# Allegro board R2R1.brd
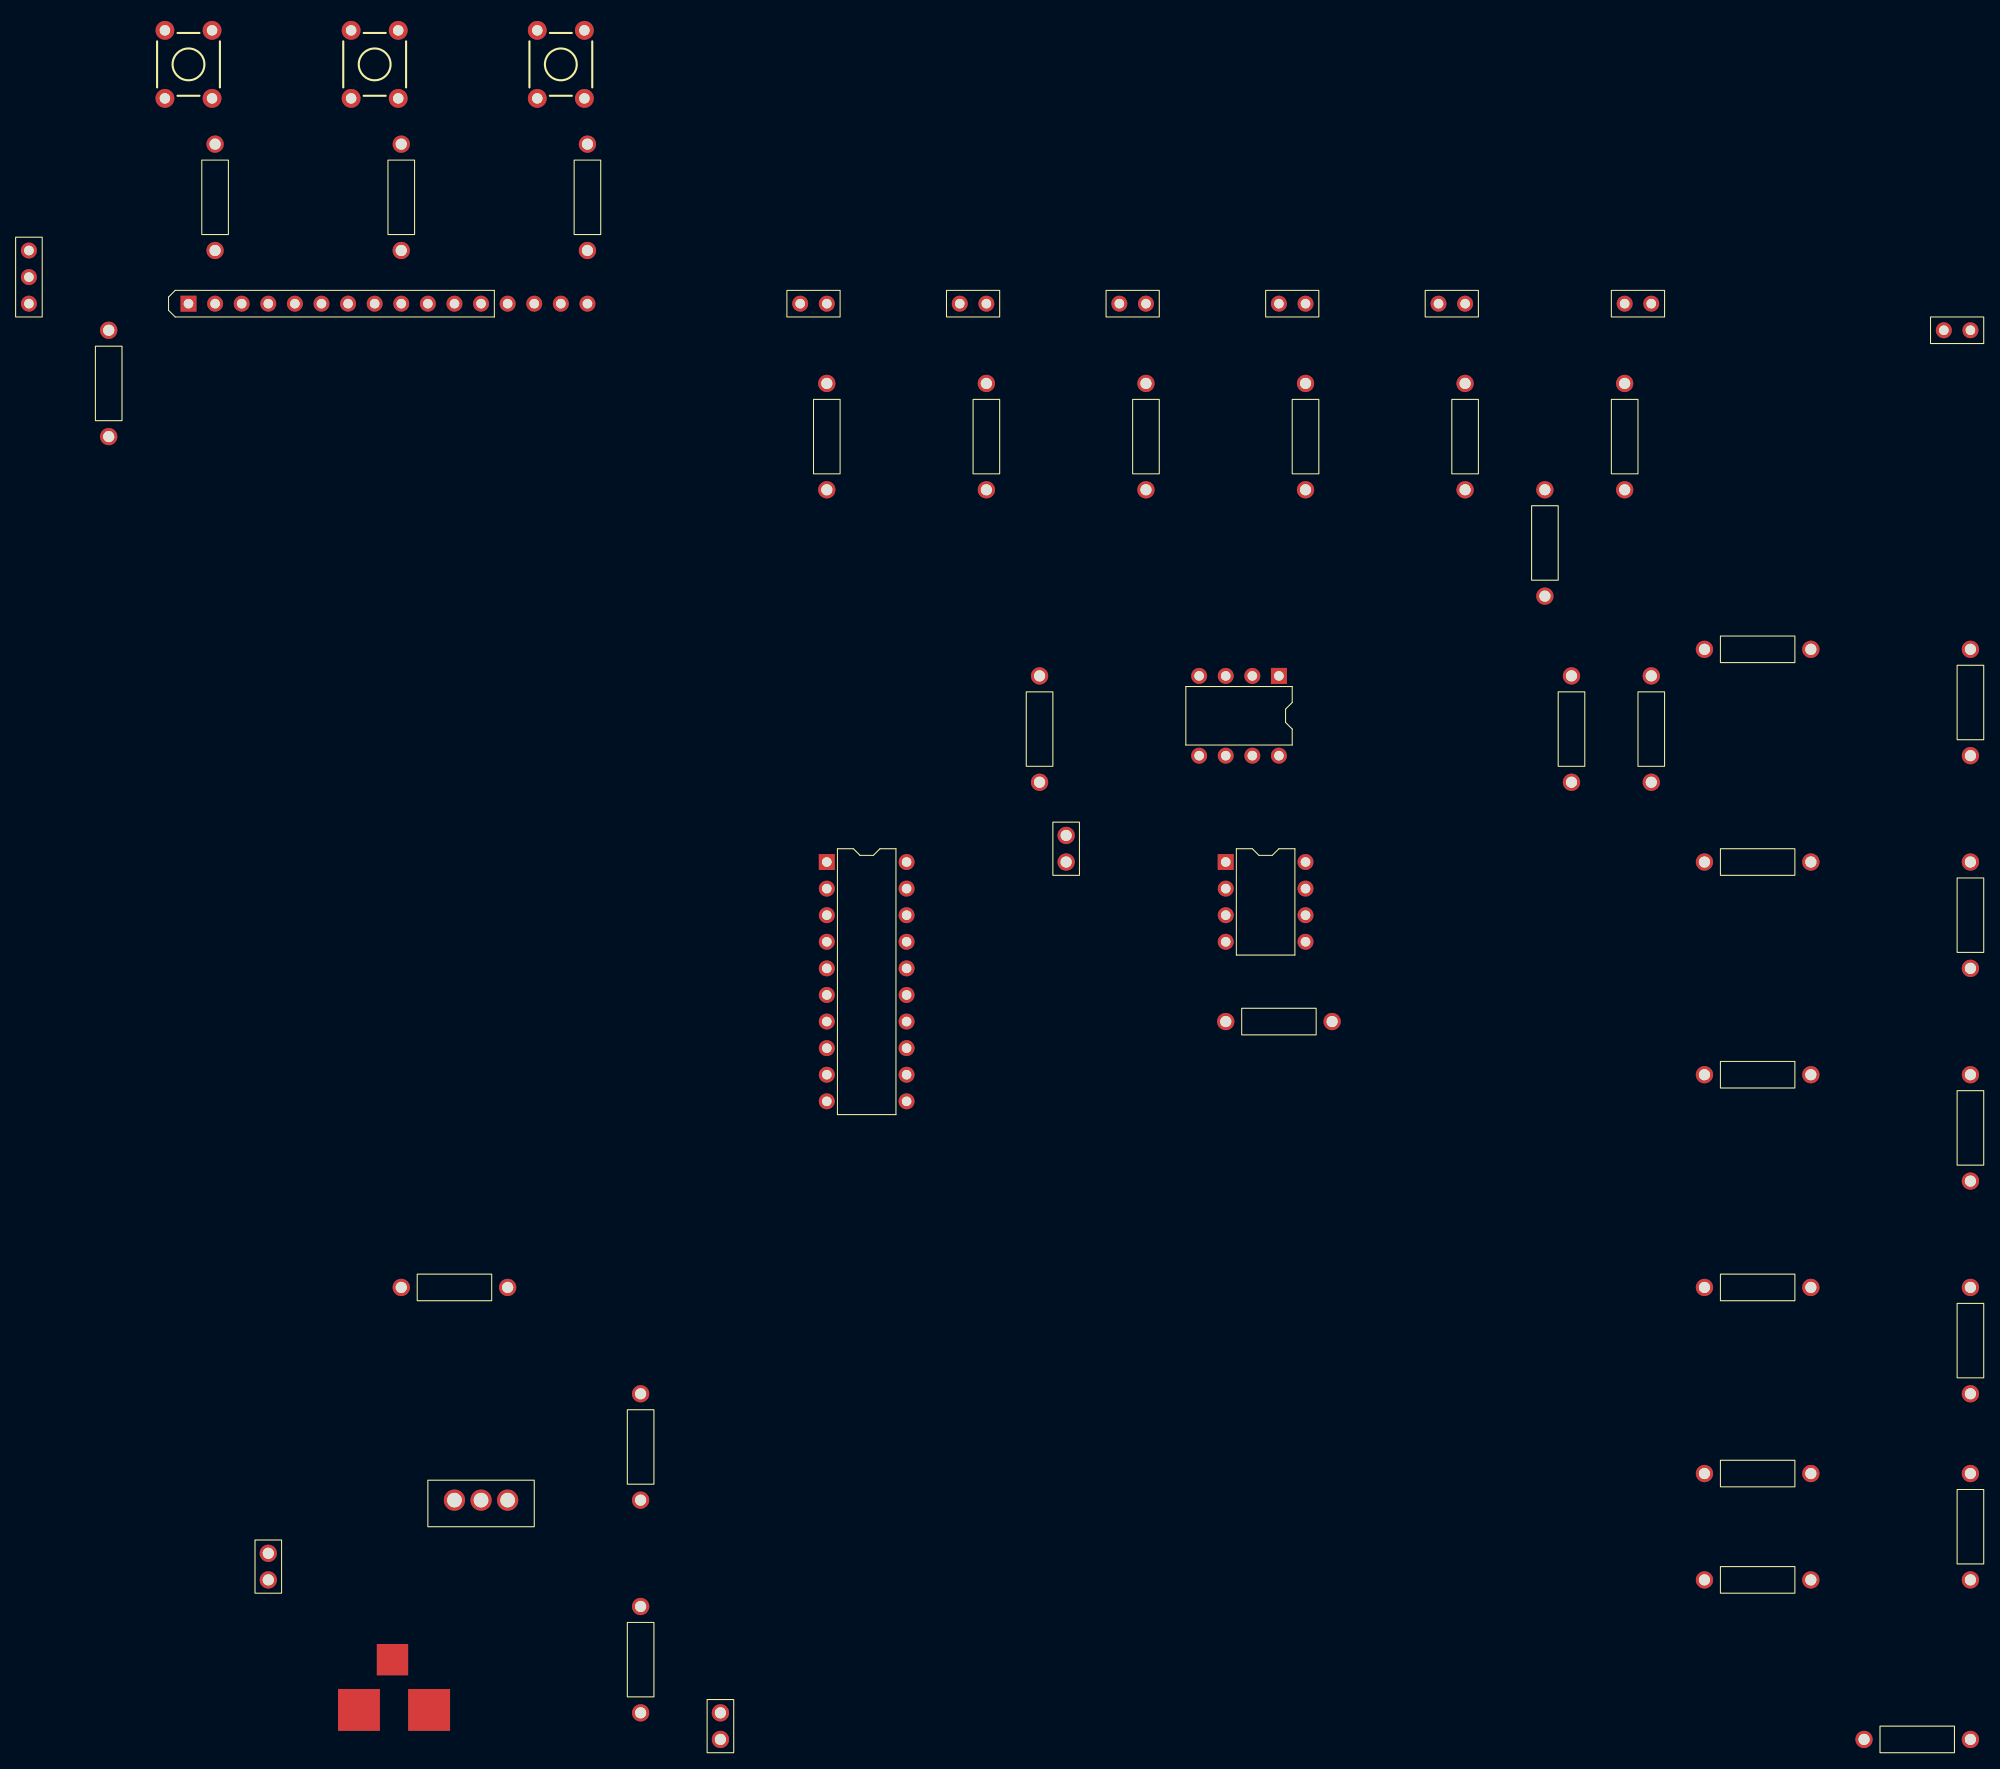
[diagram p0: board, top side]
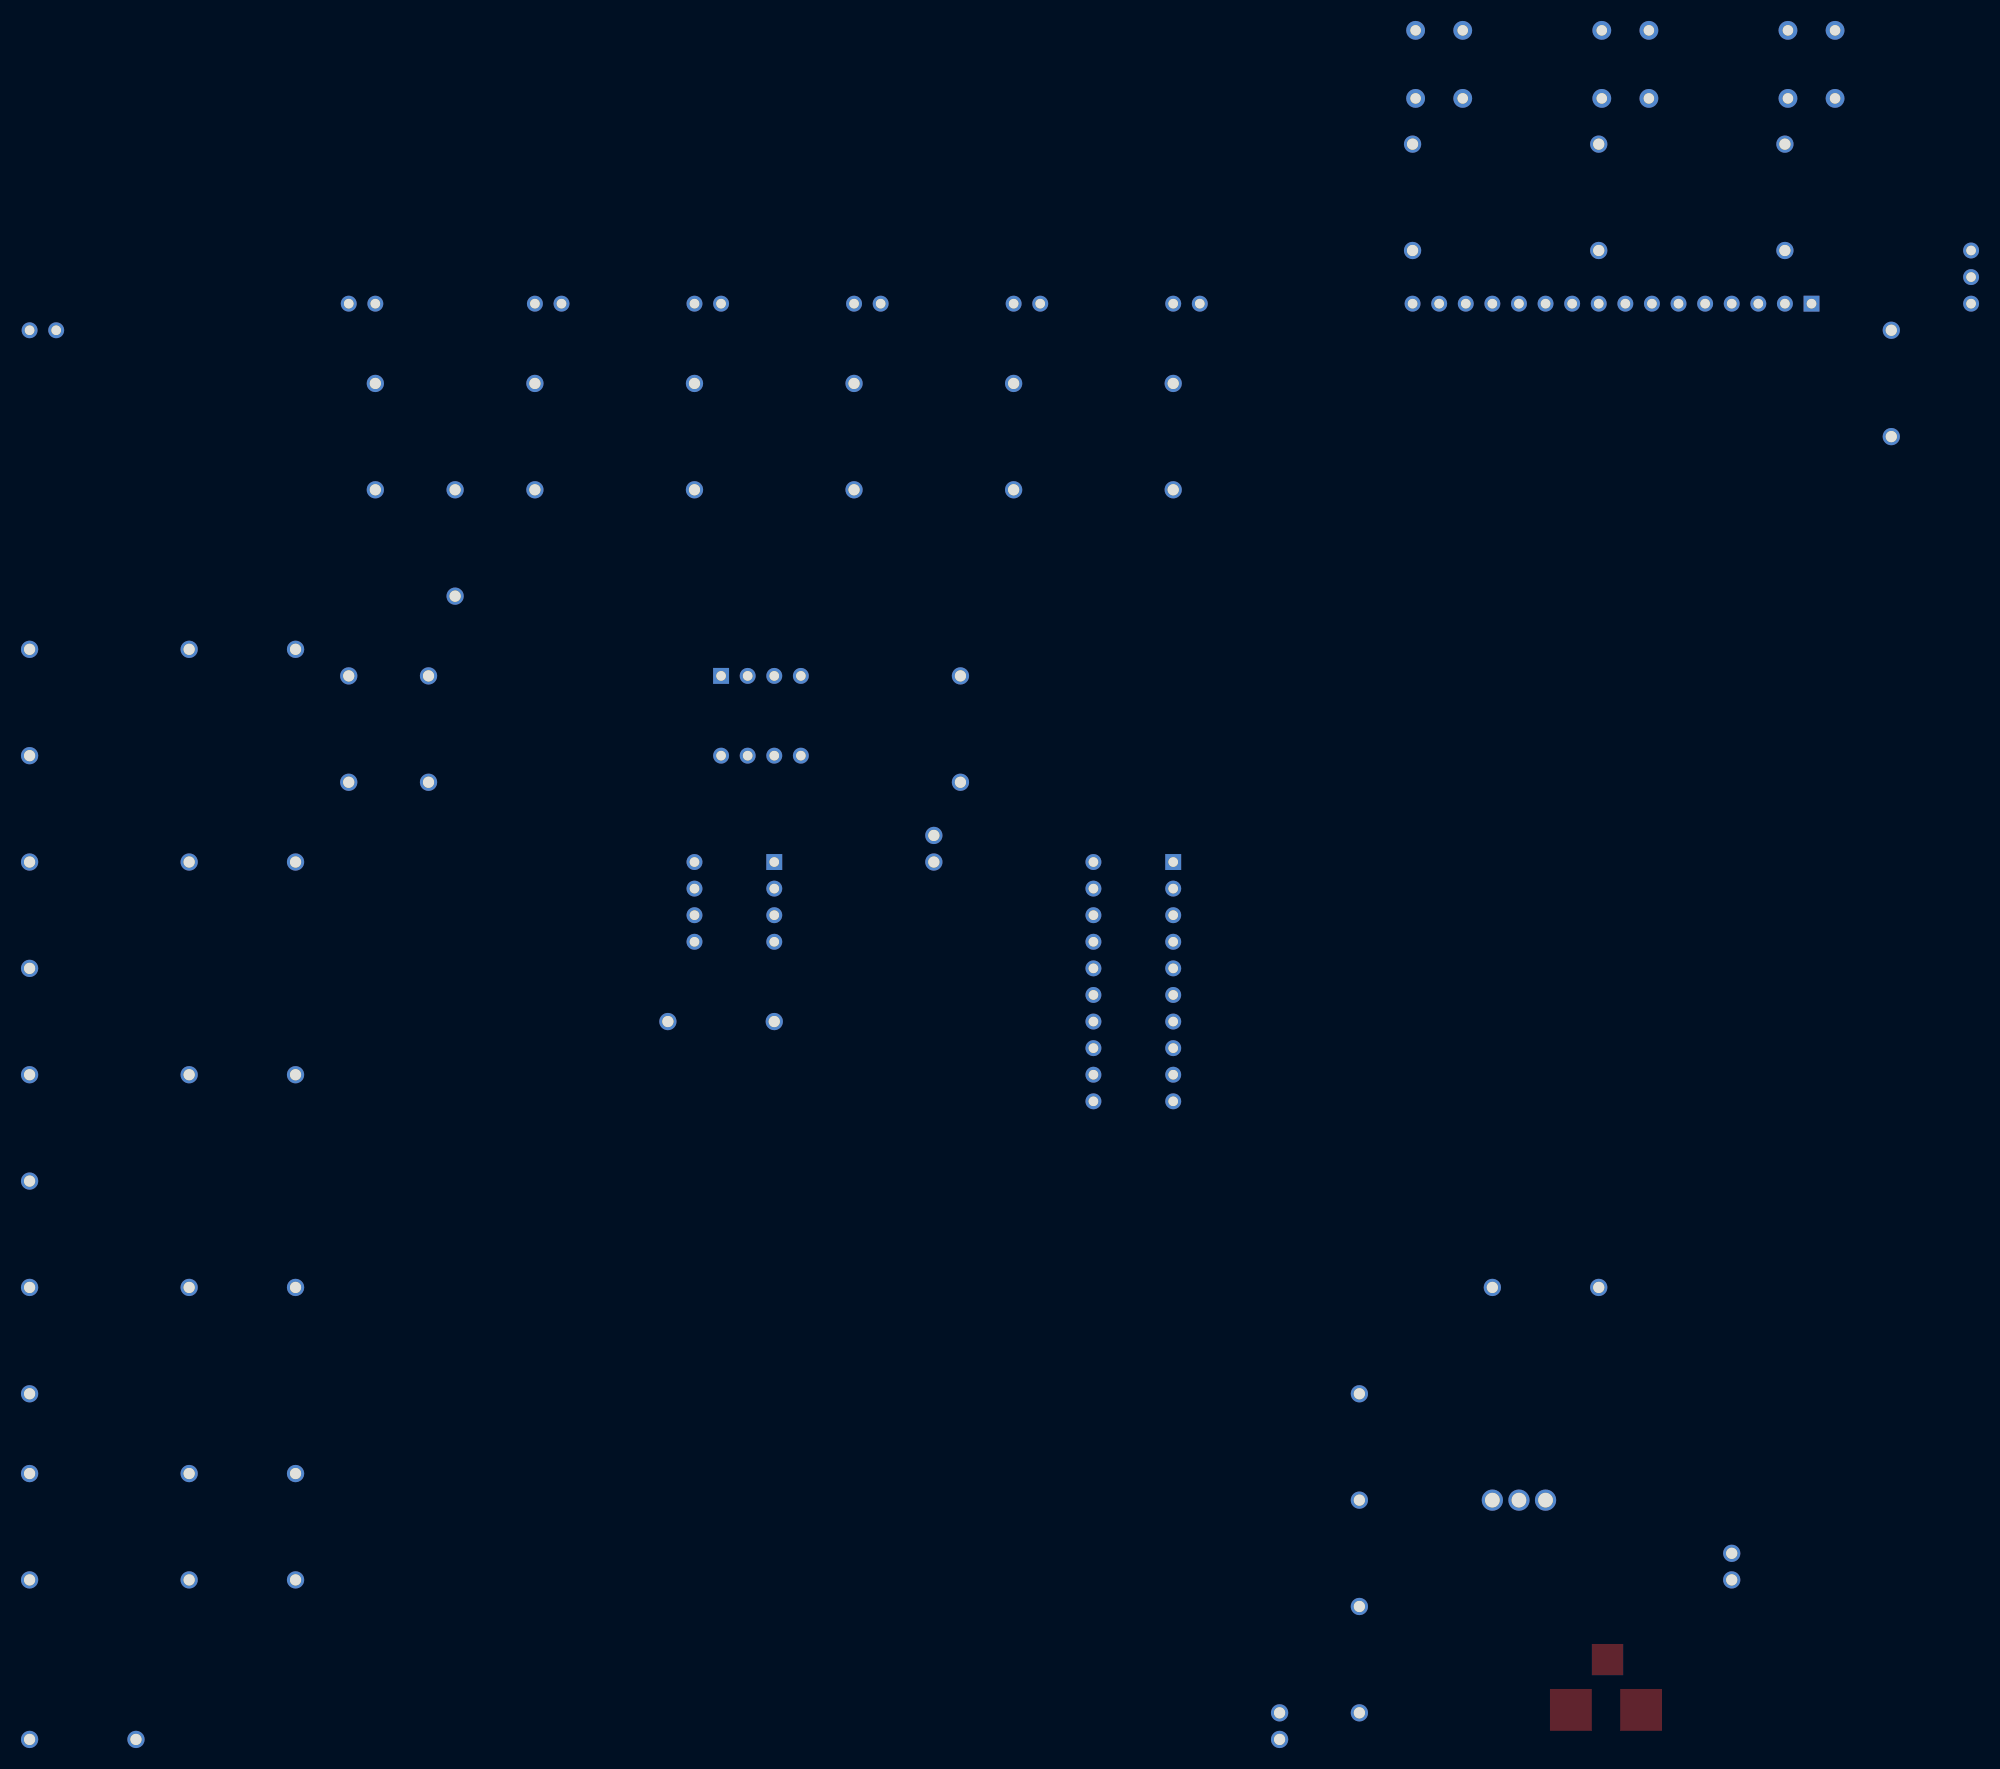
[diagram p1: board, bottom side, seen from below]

No outline. copper layers: TOP, BOTTOM. Coordinates in mm from the lowest, leftmost part position.

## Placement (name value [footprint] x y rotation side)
C3  10nf  [CAPCK05]  99.06 86.36 180 top
C4  10u  [CAPCK05]  22.86 15.24 0 top
C5  10u  [CAPCK05]  66.04 0 0 top
D1  MLED81  [JUMPER2]  73.66 137.16 0 top
D2  MLED81  [JUMPER2]  88.9 137.16 0 top
D3  MLED81  [JUMPER2]  104.14 137.16 0 top
D4  MLED81  [JUMPER2]  119.38 137.16 0 top
D5  MLED81  [JUMPER2]  134.62 137.16 0 top
D6  MLED81  [JUMPER2]  154.94 137.16 180 top
J1  Speaker  [JUMPER2]  185.42 134.62 180 top
J2  LCD 1602  [SIP16]  15.24 137.16 90 top
J3  CON3  [JACK_DC]  45.72 7.62 180 top
R2  1k  [RES400]  185.42 93.98 0 top
R3  1k  [RES400]  185.42 73.66 0 top
R4  1k  [RES400]  185.42 53.34 0 top
R5  1k  [RES400]  185.42 33.02 0 top
R6  1k  [RES400]  185.42 15.24 0 top
R7  2k  [RES400]  160.02 15.24 270 top
R8  2k  [RES400]  160.02 25.4 270 top
R9  2k  [RES400]  160.02 43.18 270 top
R10  2k  [RES400]  160.02 63.5 270 top
R11  2k  [RES400]  160.02 83.82 270 top
R12  2k  [RES400]  160.02 104.14 270 top
R13  2k  [RES400]  175.26 0 270 top
R14  470  [RES400]  152.4 119.38 0 top
R15  470  [RES400]  137.16 119.38 0 top
R16  470  [RES400]  121.92 119.38 0 top
R17  470  [RES400]  106.68 119.38 0 top
R18  470  [RES400]  91.44 119.38 0 top
R19  470  [RES400]  76.2 119.38 0 top
R20  10k  [RES400]  144.78 109.22 0 top
R22  10k  [RES400]  154.94 91.44 0 top
R23  1k  [RES400]  35.56 43.18 270 top
R24  470  [RES400]  58.42 22.86 0 top
R25  150  [RES400]  58.42 2.54 0 top
R26  33k  [RES400]  114.3 68.58 270 top
R27  10k  [RES400]  96.52 101.6 180 top
R28  10k  [RES400]  147.32 101.6 180 top
R29  1k  [JUMPER3]  0 137.16 90 top
R30  10k  [RES400]  17.78 152.4 180 top
R33  1k  [RES400]  7.62 124.46 0 top
R34  10k  [RES400]  35.56 152.4 180 top
R35  10k  [RES400]  53.34 152.4 180 top
SW7  SW_TC_SPST  [SW_SCHURTER_13019306L]  15.24 160.02 180 top
SW8  SW_TC_SPST  [SW_SCHURTER_13019306L]  33.02 160.02 180 top
SW9  SW_TC_SPST  [SW_SCHURTER_13019306L]  50.8 160.02 180 top
U1  MSP430G2553  [DIP20]  76.2 83.82 0 top
U7  LM317K  [TO220AB]  45.72 22.86 0 top
U9  LM358  [DIP8_3]  119.38 101.6 270 top
U10  LM358  [DIP8_3]  114.3 83.82 0 top

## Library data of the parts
C3-C5 = C: Tolerance: ***; User Part Number: ***
D1-D6 = MLED81: User Part Number: ***
J1 = CON2: User Part Number: ***
J2 = CON16: User Part Number: ***
J3 = CON3
R2-R20 R22-R28 R30 R33-R35 = R: Tolerance: ***; User Part Number: ***
R29 = POT: User Part Number: ***
SW7-SW9 = SW_TC_SPST
U1 = MSP430G2553_4: Tolerance: ***; User Part Number: ***
U7 = LM317T
U9 = LM358: Tolerance: ***; User Part Number: ***
U10 = LM358_0: Tolerance: ***; User Part Number: ***

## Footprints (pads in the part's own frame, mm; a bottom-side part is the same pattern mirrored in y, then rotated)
CAPCK05
  round 1.651 hole 1.067: 1(0,0) 2(0,2.54)
DIP8_3
  rect 1.524x1.524 hole 0.914: 1(0,0)
  round 1.524 hole 0.914: 2(0,-2.54) 3(0,-5.08) 4(0,-7.62) 5(7.62,-7.62) 6(7.62,-5.08) 7(7.62,-2.54) 8(7.62,0)
DIP20
  rect 1.524x1.524 hole 0.914: 1(0,0)
  round 1.524 hole 0.914: 2(0,-2.54) 3(0,-5.08) 4(0,-7.62) 5(0,-10.16) 6(0,-12.7) 7(0,-15.24) 8(0,-17.78) 9(0,-20.32) 10(0,-22.86) 11(7.62,-22.86) 12(7.62,-20.32) 13(7.62,-17.78) 14(7.62,-15.24) 15(7.62,-12.7) 16(7.62,-10.16) 17(7.62,-7.62) 18(7.62,-5.08) 19(7.62,-2.54) 20(7.62,0)
JACK_DC
  rect 4x4 smd: 1(7.5,4.8) 2(14.2,4.8)
  rect 3x3 smd: 3(11,0)
JUMPER2
  round 1.524 hole 0.914: 1(0,0) 2(2.54,0)
JUMPER3
  round 1.524 hole 0.914: 1(0,0) 2(2.54,0) 3(5.08,0)
RES400
  round 1.651 hole 1.067: 1(0,0) 2(0,10.16)
SIP16
  rect 1.524x1.524 hole 0.914: 1(0,0)
  round 1.524 hole 0.914: 2(0,-2.54) 3(0,-5.08) 4(0,-7.62) 5(0,-10.16) 6(0,-12.7) 7(0,-15.24) 8(0,-17.78) 9(0,-20.32) 10(0,-22.86) 11(0,-25.4) 12(0,-27.94) 13(0,-30.48) 14(0,-33.02) 15(0,-35.56) 16(0,-38.1)
SW_SCHURTER_13019306L
  round 1.8 hole 1: 1(-2.25,-3.25) 2(-2.25,3.25) 3(2.25,3.25) 4(2.25,-3.25)
TO220AB
  round 2.032 hole 1.397: 1(0,0) 2(-2.54,0) 3(-5.08,0)

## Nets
9V: C4.1 J3.1 U9.8(V+)
VCC: C5.2 J2.2 J2.16 R24.2 R30.2 R33.1 R34.2 R35.2 U1.1(DVCC) U7.3(OUT)
0: C3.2 C5.1 J2.1 J2.5 J3.2 J3.3 R13.1 R14.1 R15.1 R16.1 R17.1 R18.1 R19.1 R20.2 R23.1 R29.1 SW7.3 SW8.3 SW9.3 U1.20(GROUND) U9.4(V-) U9.5(+)
SW1: R30.1 SW7.1 SW7.2 U1.8(P2_0/CS(B0))
SW2: R34.1 SW8.1 SW8.2 U1.9(P2_1)
SW3: R35.1 SW9.1 SW9.2 U1.10(P2_2)
V+: U10.8(V+)
V-: U10.4(V-)
N00328: R2.1 R3.2 R11.2
N00332: R3.1 R4.2 R10.2
N00336: R4.1 R5.2 R9.2
N00340: R5.1 R6.2 R8.2
N00355: R2.2 R12.2 U10.3(+)
N00470: R6.1 R7.2 R13.2
N01662: D1.1(A) D2.1(A) D3.1(A) D4.1(A) D5.1(A) D6.1(A) R7.1 R8.1 R9.1 R10.1 R11.1 R12.1 U1.2(P1_0/A0/RED_LED) U1.3(P1_1/A1/RXD) U1.4(P1_2/A2/TXD) U1.5(P1_3/A3/PUSH2) U1.6(P1_4/A4) U1.7(P1_5/A5/SCK(B0))
N006340: D6.2(C) R14.2
N006500: D5.2(C) R15.2
N006660: D4.2(C) R16.2
N006820: D3.2(C) R17.2
N006980: D2.2(C) R18.2
N007140: D1.2(C) R19.2
N20855: R23.2 R25.1 U7.1(ADJ)
N23488: C3.1 R26.2 U9.3(+)
N23661: R26.1 U10.1(OUT) U10.2(-)
N24189: R20.1 R27.2 U9.2(-)
N24193: J1.1 R22.2 R27.1 U9.1(OUT)
N25824: R22.1 R28.2 U9.6(-)
N25853: J1.2 R28.1 U9.7(OUT)
N28143: C4.2 U7.2(IN)
N35057: J2.3 R29.2(T) R29.3(2)
N35516: J2.4 U1.11(P2_3)
N35592: J2.6 U1.12(P2_4)
N35638: J2.11 U1.13(P2_5)
N35656: J2.12 U1.14(P1_6/A6/SCL/MISO(B0)/GREEN LED)
N35674: J2.13 U1.15(P1_7/A7/SDA/MOSE(B0))
N35692: J2.14 U1.18(P2_7/XOUT)
N35721: J2.15 R33.2
N209781: R24.1 R25.2

Pads without a net: J2 7 8 9 10; SW7 4; SW8 4; SW9 4; U1 16 17 19; U10 5 6 7
